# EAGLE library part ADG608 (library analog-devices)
3 V/5 V, 8 Channel High Performance Analog Multiplexers Source: ADG608_609.pdf
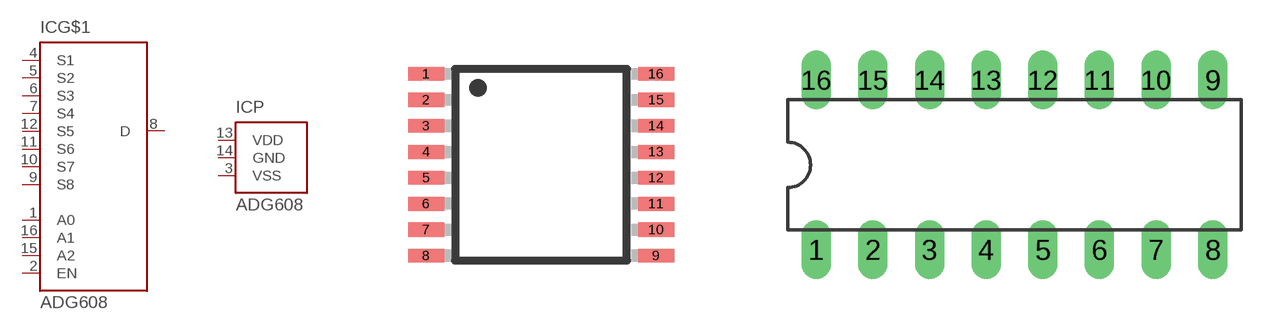
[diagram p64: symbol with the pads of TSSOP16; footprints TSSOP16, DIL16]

Designator prefix IC; gates G$1=ADG1408 P=PWR-VSS_GND_VDD

## ADG608RU (MF: ALTERA CORPORATION; MPN: ADG608BRU; OC_FARNELL: 1465227; OC_NEWARK: 16F6552)  [TSSOP16]
1  G$1:A0  in
2  G$1:EN  in
3  P:VSS  pwr
4  G$1:S1
5  G$1:S2
6  G$1:S3
7  G$1:S4
8  G$1:D
9  G$1:S8
10  G$1:S7
11  G$1:S6
12  G$1:S5
13  P:VDD  pwr
14  P:GND  pwr
15  G$1:A2  in
16  G$1:A1  in

## ADG608N (MPN: ADG608BNZ; OC_FARNELL: 1438944; OC_NEWARK: 15P0383)  [DIL16]
Pads as for TSSOP16

## ADG608R (MF: ALTERA CORPORATION; MPN: ADG608BR; OC_FARNELL: 1438944; OC_NEWARK: 09B7118)  [SOIC16N]
Pads as for TSSOP16

## Footprint TSSOP16 (pad centres in mm)
16-Lead Thin Shrink Small Outline Package [TSSOP] (RU-16) Source: 8x ADG1408_1409.pdf
smd 0.9 x 0.35: 1 -2.875,2.275; 2 -2.875,1.625; 3 -2.875,0.975; 4 -2.875,0.325; 5 -2.875,-0.325; 6 -2.875,-0.975; 7 -2.875,-1.625; 8 -2.875,-2.275; 9 2.875,-2.275; 10 2.875,-1.625; 11 2.875,-0.975; 12 2.875,-0.325; 13 2.875,0.325; 14 2.875,0.975; 15 2.875,1.625; 16 2.875,2.275

## Footprint DIL16 (pad centres in mm)
Dual In Line Package
drill 0.813 long: 1 -8.89,-3.81; 2 -6.35,-3.81; 3 -3.81,-3.81; 4 -1.27,-3.81; 5 1.27,-3.81; 6 3.81,-3.81; 7 6.35,-3.81; 8 8.89,-3.81; 9 8.89,3.81; 10 6.35,3.81; 11 3.81,3.81; 12 1.27,3.81; 13 -1.27,3.81; 14 -3.81,3.81; 15 -6.35,3.81; 16 -8.89,3.81

## Footprint SOIC16N (pad centres in mm)
SMALL OUTLINE INTEGRATED CIRCUIT
smd 0.6 x 2.2: 1 -4.445,-2.6; 2 -3.175,-2.6; 3 -1.905,-2.6; 4 -0.635,-2.6; 5 0.635,-2.6; 6 1.905,-2.6; 7 3.175,-2.6; 8 4.445,-2.6; 9 4.445,2.6; 10 3.175,2.6; 11 1.905,2.6; 12 0.635,2.6; 13 -0.635,2.6; 14 -1.905,2.6; 15 -3.175,2.6; 16 -4.445,2.6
